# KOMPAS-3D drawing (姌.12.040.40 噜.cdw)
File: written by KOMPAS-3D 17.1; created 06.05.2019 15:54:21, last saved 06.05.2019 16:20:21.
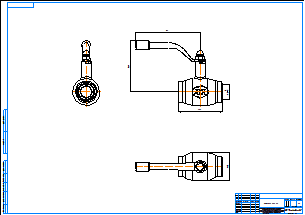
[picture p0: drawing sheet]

Sheet 1: A1, landscape

Title block, sheet 1: name: КШ.12.040.40 рр; material: Внимание! Данный продукт является объектом авторского права ООО «Торговый Дом АДЛ». / Запрещается изменение, копирование, распространение / (в том числе путем копирования на другие сайты и ресурсы в Интернете) / или любое иное использование информации и объектов без предварительного / согласия правообладателя (ООО «Торговый Дом АДЛ»).; scale: 1:1; sheets: 1; organisation: ООО "Торговый дом АДЛ"; sheet format: A1; stored path: C:\Users\tra\Desktop\2д чертежи\Шаровые краны БИВАЛ\КШ_Бивал_серия_11_12\KOMPAS_2D\КШ.12.040.40 рр.cdw

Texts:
  user
Dimensions and other numbers on the sheet: 120; 142; 180; 76,1; 1:1; 1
